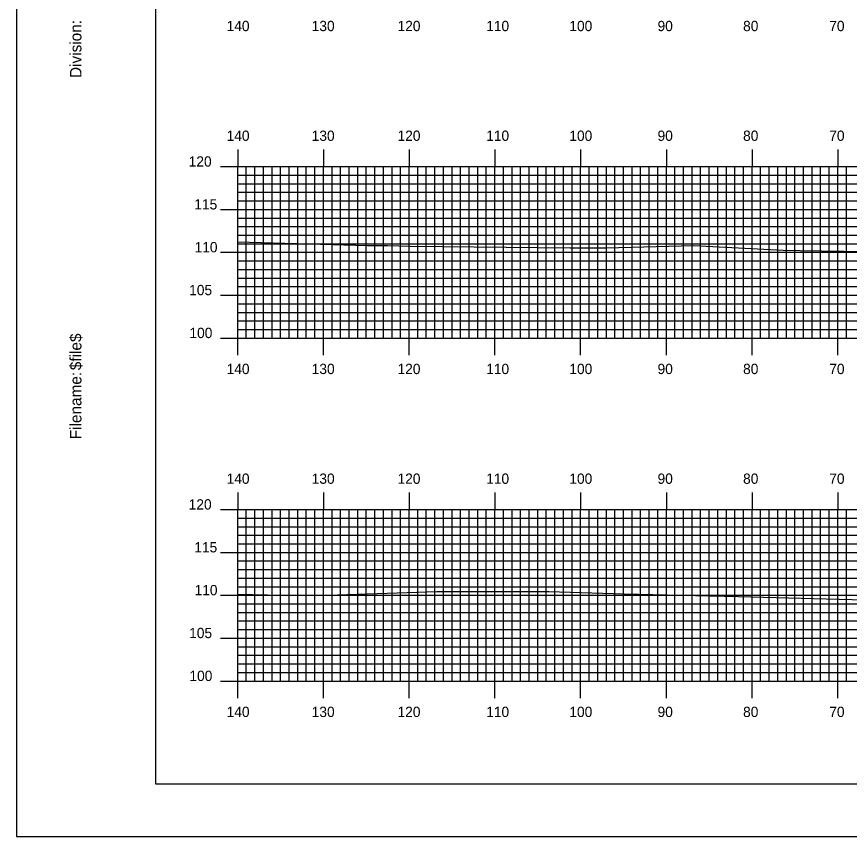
# Model space of a CAD drawing. Extents: x 1779499 to 1779842, y 442591 to 442811.
# Drawn here: x 1779499.1 to 1779596.2, y 442590.5 to 442686.2 of the extents above; entities that cross this region are included whole.
import ezdxf

# ---------------------------------------------------------------- set-up
doc = ezdxf.new("R2010")
doc.units = 0
for name, color, linetype in [('BORDER', 7, 'Continuous'), ('H_V ANNOTATION', 7, 'Continuous'), ('MAJOR', 7, 'Continuous'), ('MINOR', 7, 'Continuous'), ('PLOT BOUNDARY', 7, 'Continuous'), ('S_Roadway_Centerline', 7, 'Continuous')]:
    doc.layers.add(name, color=color, linetype=linetype)

msp = doc.modelspace()

# ---------------------------------------------------------------- linework, layer by layer
at = {"layer": 'BORDER'}
msp.add_lwpolyline([(1779515.242, 442596.665), (1779835.242, 442596.665), (1779835.242, 442806.665), (1779515.242, 442806.665)], close=True, dxfattribs=at)
at = {"layer": 'MAJOR'}
for p, q in [((1779524.842, 442670.669), (1779524.842, 442668.665)), ((1779534.842, 442670.669), (1779534.842, 442668.665)), ((1779544.842, 442670.669), (1779544.842, 442668.665)), ((1779554.842, 442670.669), (1779554.842, 442668.665)), ((1779564.842, 442670.669), (1779564.842, 442668.665)), ((1779574.842, 442670.669), (1779574.842, 442668.665)), ((1779584.842, 442670.669), (1779584.842, 442668.665)), ((1779594.842, 442670.669), (1779594.842, 442668.665)), ((1779522.838, 442668.665), (1779524.842, 442668.665)), ((1779524.842, 442668.665), (1779804.842, 442668.665)), ((1779524.842, 442648.665), (1779524.842, 442668.665)), ((1779524.842, 442648.665), (1779524.842, 442668.665)), ((1779524.842, 442668.665), (1779804.842, 442668.665)), ((1779534.842, 442648.665), (1779534.842, 442668.665)), ((1779544.842, 442648.665), (1779544.842, 442668.665)), ((1779554.842, 442648.665), (1779554.842, 442668.665)), ((1779564.842, 442648.665), (1779564.842, 442668.665)), ((1779574.842, 442648.665), (1779574.842, 442668.665)), ((1779584.842, 442648.665), (1779584.842, 442668.665)), ((1779594.842, 442648.665), (1779594.842, 442668.665)), ((1779522.838, 442663.665), (1779524.842, 442663.665)), ((1779524.842, 442663.665), (1779804.842, 442663.665)), ((1779522.838, 442658.665), (1779524.842, 442658.665)), ((1779524.842, 442658.665), (1779804.842, 442658.665)), ((1779522.838, 442653.665), (1779524.842, 442653.665)), ((1779524.842, 442653.665), (1779804.842, 442653.665)), ((1779522.838, 442648.665), (1779524.842, 442648.665)), ((1779524.842, 442648.665), (1779804.842, 442648.665)), ((1779524.842, 442648.665), (1779804.842, 442648.665)), ((1779524.842, 442646.661), (1779524.842, 442648.665)), ((1779534.842, 442646.661), (1779534.842, 442648.665)), ((1779544.842, 442646.661), (1779544.842, 442648.665)), ((1779554.842, 442646.661), (1779554.842, 442648.665)), ((1779564.842, 442646.661), (1779564.842, 442648.665)), ((1779574.842, 442646.661), (1779574.842, 442648.665)), ((1779584.842, 442646.661), (1779584.842, 442648.665)), ((1779594.842, 442646.661), (1779594.842, 442648.665)), ((1779524.842, 442630.669), (1779524.842, 442628.665)), ((1779534.842, 442630.669), (1779534.842, 442628.665)), ((1779544.842, 442630.669), (1779544.842, 442628.665)), ((1779554.842, 442630.669), (1779554.842, 442628.665)), ((1779564.842, 442630.669), (1779564.842, 442628.665)), ((1779574.842, 442630.669), (1779574.842, 442628.665)), ((1779584.842, 442630.669), (1779584.842, 442628.665)), ((1779594.842, 442630.669), (1779594.842, 442628.665)), ((1779522.838, 442628.665), (1779524.842, 442628.665)), ((1779524.842, 442628.665), (1779804.842, 442628.665)), ((1779524.842, 442608.665), (1779524.842, 442628.665)), ((1779524.842, 442608.665), (1779524.842, 442628.665)), ((1779524.842, 442628.665), (1779804.842, 442628.665)), ((1779534.842, 442608.665), (1779534.842, 442628.665)), ((1779544.842, 442608.665), (1779544.842, 442628.665)), ((1779554.842, 442608.665), (1779554.842, 442628.665)), ((1779564.842, 442608.665), (1779564.842, 442628.665)), ((1779574.842, 442608.665), (1779574.842, 442628.665)), ((1779584.842, 442608.665), (1779584.842, 442628.665)), ((1779594.842, 442608.665), (1779594.842, 442628.665)), ((1779522.838, 442623.665), (1779524.842, 442623.665)), ((1779524.842, 442623.665), (1779804.842, 442623.665)), ((1779522.838, 442618.665), (1779524.842, 442618.665)), ((1779524.842, 442618.665), (1779804.842, 442618.665)), ((1779522.838, 442613.665), (1779524.842, 442613.665)), ((1779524.842, 442613.665), (1779804.842, 442613.665)), ((1779522.838, 442608.665), (1779524.842, 442608.665)), ((1779524.842, 442608.665), (1779804.842, 442608.665)), ((1779524.842, 442608.665), (1779804.842, 442608.665)), ((1779524.842, 442606.661), (1779524.842, 442608.665)), ((1779534.842, 442606.661), (1779534.842, 442608.665)), ((1779544.842, 442606.661), (1779544.842, 442608.665)), ((1779554.842, 442606.661), (1779554.842, 442608.665)), ((1779564.842, 442606.661), (1779564.842, 442608.665)), ((1779574.842, 442606.661), (1779574.842, 442608.665)), ((1779584.842, 442606.661), (1779584.842, 442608.665)), ((1779594.842, 442606.661), (1779594.842, 442608.665))]:
    msp.add_line(p, q, dxfattribs=at)
at = {"layer": 'MINOR'}
for p, q in [((1779525.842, 442648.665), (1779525.842, 442668.665)), ((1779526.842, 442648.665), (1779526.842, 442668.665)), ((1779527.842, 442648.665), (1779527.842, 442668.665)), ((1779528.842, 442648.665), (1779528.842, 442668.665)), ((1779529.842, 442648.665), (1779529.842, 442668.665)), ((1779530.842, 442648.665), (1779530.842, 442668.665)), ((1779531.842, 442648.665), (1779531.842, 442668.665)), ((1779532.842, 442648.665), (1779532.842, 442668.665)), ((1779533.842, 442648.665), (1779533.842, 442668.665)), ((1779535.842, 442648.665), (1779535.842, 442668.665)), ((1779536.842, 442648.665), (1779536.842, 442668.665)), ((1779537.842, 442648.665), (1779537.842, 442668.665)), ((1779538.842, 442648.665), (1779538.842, 442668.665)), ((1779539.842, 442648.665), (1779539.842, 442668.665)), ((1779540.842, 442648.665), (1779540.842, 442668.665)), ((1779541.842, 442648.665), (1779541.842, 442668.665)), ((1779542.842, 442648.665), (1779542.842, 442668.665)), ((1779543.842, 442648.665), (1779543.842, 442668.665)), ((1779545.842, 442648.665), (1779545.842, 442668.665)), ((1779546.842, 442648.665), (1779546.842, 442668.665)), ((1779547.842, 442648.665), (1779547.842, 442668.665)), ((1779548.842, 442648.665), (1779548.842, 442668.665)), ((1779549.842, 442648.665), (1779549.842, 442668.665)), ((1779550.842, 442648.665), (1779550.842, 442668.665)), ((1779551.842, 442648.665), (1779551.842, 442668.665)), ((1779552.842, 442648.665), (1779552.842, 442668.665)), ((1779553.842, 442648.665), (1779553.842, 442668.665)), ((1779555.842, 442648.665), (1779555.842, 442668.665)), ((1779556.842, 442648.665), (1779556.842, 442668.665)), ((1779557.842, 442648.665), (1779557.842, 442668.665)), ((1779558.842, 442648.665), (1779558.842, 442668.665)), ((1779559.842, 442648.665), (1779559.842, 442668.665)), ((1779560.842, 442648.665), (1779560.842, 442668.665)), ((1779561.842, 442648.665), (1779561.842, 442668.665)), ((1779562.842, 442648.665), (1779562.842, 442668.665)), ((1779563.842, 442648.665), (1779563.842, 442668.665)), ((1779565.842, 442648.665), (1779565.842, 442668.665)), ((1779566.842, 442648.665), (1779566.842, 442668.665)), ((1779567.842, 442648.665), (1779567.842, 442668.665)), ((1779568.842, 442648.665), (1779568.842, 442668.665)), ((1779569.842, 442648.665), (1779569.842, 442668.665)), ((1779570.842, 442648.665), (1779570.842, 442668.665)), ((1779571.842, 442648.665), (1779571.842, 442668.665)), ((1779572.842, 442648.665), (1779572.842, 442668.665)), ((1779573.842, 442648.665), (1779573.842, 442668.665)), ((1779575.842, 442648.665), (1779575.842, 442668.665)), ((1779576.842, 442648.665), (1779576.842, 442668.665)), ((1779577.842, 442648.665), (1779577.842, 442668.665)), ((1779578.842, 442648.665), (1779578.842, 442668.665)), ((1779579.842, 442648.665), (1779579.842, 442668.665)), ((1779580.842, 442648.665), (1779580.842, 442668.665)), ((1779581.842, 442648.665), (1779581.842, 442668.665)), ((1779582.842, 442648.665), (1779582.842, 442668.665)), ((1779583.842, 442648.665), (1779583.842, 442668.665)), ((1779585.842, 442648.665), (1779585.842, 442668.665)), ((1779586.842, 442648.665), (1779586.842, 442668.665)), ((1779587.842, 442648.665), (1779587.842, 442668.665)), ((1779588.842, 442648.665), (1779588.842, 442668.665)), ((1779589.842, 442648.665), (1779589.842, 442668.665)), ((1779590.842, 442648.665), (1779590.842, 442668.665)), ((1779591.842, 442648.665), (1779591.842, 442668.665)), ((1779592.842, 442648.665), (1779592.842, 442668.665)), ((1779593.842, 442648.665), (1779593.842, 442668.665)), ((1779595.842, 442648.665), (1779595.842, 442668.665)), ((1779524.842, 442667.665), (1779804.842, 442667.665)), ((1779524.842, 442667.665), (1779526.846, 442667.665)), ((1779524.842, 442666.665), (1779804.842, 442666.665)), ((1779524.842, 442666.665), (1779526.846, 442666.665)), ((1779524.842, 442665.665), (1779804.842, 442665.665)), ((1779524.842, 442665.665), (1779526.846, 442665.665)), ((1779524.842, 442664.665), (1779804.842, 442664.665)), ((1779524.842, 442664.665), (1779526.846, 442664.665)), ((1779524.842, 442662.665), (1779804.842, 442662.665)), ((1779524.842, 442662.665), (1779526.846, 442662.665)), ((1779524.842, 442661.665), (1779804.842, 442661.665)), ((1779524.842, 442661.665), (1779526.846, 442661.665)), ((1779524.842, 442660.665), (1779804.842, 442660.665)), ((1779524.842, 442660.665), (1779526.846, 442660.665)), ((1779524.842, 442659.665), (1779804.842, 442659.665)), ((1779524.842, 442659.665), (1779526.846, 442659.665)), ((1779524.842, 442657.665), (1779804.842, 442657.665)), ((1779524.842, 442657.665), (1779526.846, 442657.665)), ((1779524.842, 442656.665), (1779804.842, 442656.665)), ((1779524.842, 442656.665), (1779526.846, 442656.665)), ((1779524.842, 442655.665), (1779804.842, 442655.665)), ((1779524.842, 442655.665), (1779526.846, 442655.665)), ((1779524.842, 442654.665), (1779804.842, 442654.665)), ((1779524.842, 442654.665), (1779526.846, 442654.665)), ((1779524.842, 442652.665), (1779804.842, 442652.665)), ((1779524.842, 442652.665), (1779526.846, 442652.665)), ((1779524.842, 442651.665), (1779804.842, 442651.665)), ((1779524.842, 442651.665), (1779526.846, 442651.665)), ((1779524.842, 442650.665), (1779804.842, 442650.665)), ((1779524.842, 442650.665), (1779526.846, 442650.665)), ((1779524.842, 442649.665), (1779804.842, 442649.665)), ((1779524.842, 442649.665), (1779526.846, 442649.665)), ((1779525.842, 442608.665), (1779525.842, 442628.665)), ((1779526.842, 442608.665), (1779526.842, 442628.665)), ((1779527.842, 442608.665), (1779527.842, 442628.665)), ((1779528.842, 442608.665), (1779528.842, 442628.665)), ((1779529.842, 442608.665), (1779529.842, 442628.665)), ((1779530.842, 442608.665), (1779530.842, 442628.665)), ((1779531.842, 442608.665), (1779531.842, 442628.665)), ((1779532.842, 442608.665), (1779532.842, 442628.665)), ((1779533.842, 442608.665), (1779533.842, 442628.665)), ((1779535.842, 442608.665), (1779535.842, 442628.665)), ((1779536.842, 442608.665), (1779536.842, 442628.665)), ((1779537.842, 442608.665), (1779537.842, 442628.665)), ((1779538.842, 442608.665), (1779538.842, 442628.665)), ((1779539.842, 442608.665), (1779539.842, 442628.665)), ((1779540.842, 442608.665), (1779540.842, 442628.665)), ((1779541.842, 442608.665), (1779541.842, 442628.665)), ((1779542.842, 442608.665), (1779542.842, 442628.665)), ((1779543.842, 442608.665), (1779543.842, 442628.665)), ((1779545.842, 442608.665), (1779545.842, 442628.665)), ((1779546.842, 442608.665), (1779546.842, 442628.665)), ((1779547.842, 442608.665), (1779547.842, 442628.665)), ((1779548.842, 442608.665), (1779548.842, 442628.665)), ((1779549.842, 442608.665), (1779549.842, 442628.665)), ((1779550.842, 442608.665), (1779550.842, 442628.665)), ((1779551.842, 442608.665), (1779551.842, 442628.665)), ((1779552.842, 442608.665), (1779552.842, 442628.665)), ((1779553.842, 442608.665), (1779553.842, 442628.665)), ((1779555.842, 442608.665), (1779555.842, 442628.665)), ((1779556.842, 442608.665), (1779556.842, 442628.665)), ((1779557.842, 442608.665), (1779557.842, 442628.665)), ((1779558.842, 442608.665), (1779558.842, 442628.665)), ((1779559.842, 442608.665), (1779559.842, 442628.665)), ((1779560.842, 442608.665), (1779560.842, 442628.665)), ((1779561.842, 442608.665), (1779561.842, 442628.665)), ((1779562.842, 442608.665), (1779562.842, 442628.665)), ((1779563.842, 442608.665), (1779563.842, 442628.665)), ((1779565.842, 442608.665), (1779565.842, 442628.665)), ((1779566.842, 442608.665), (1779566.842, 442628.665)), ((1779567.842, 442608.665), (1779567.842, 442628.665)), ((1779568.842, 442608.665), (1779568.842, 442628.665)), ((1779569.842, 442608.665), (1779569.842, 442628.665)), ((1779570.842, 442608.665), (1779570.842, 442628.665)), ((1779571.842, 442608.665), (1779571.842, 442628.665)), ((1779572.842, 442608.665), (1779572.842, 442628.665)), ((1779573.842, 442608.665), (1779573.842, 442628.665)), ((1779575.842, 442608.665), (1779575.842, 442628.665)), ((1779576.842, 442608.665), (1779576.842, 442628.665)), ((1779577.842, 442608.665), (1779577.842, 442628.665)), ((1779578.842, 442608.665), (1779578.842, 442628.665)), ((1779579.842, 442608.665), (1779579.842, 442628.665)), ((1779580.842, 442608.665), (1779580.842, 442628.665)), ((1779581.842, 442608.665), (1779581.842, 442628.665)), ((1779582.842, 442608.665), (1779582.842, 442628.665)), ((1779583.842, 442608.665), (1779583.842, 442628.665)), ((1779585.842, 442608.665), (1779585.842, 442628.665)), ((1779586.842, 442608.665), (1779586.842, 442628.665)), ((1779587.842, 442608.665), (1779587.842, 442628.665)), ((1779588.842, 442608.665), (1779588.842, 442628.665)), ((1779589.842, 442608.665), (1779589.842, 442628.665)), ((1779590.842, 442608.665), (1779590.842, 442628.665)), ((1779591.842, 442608.665), (1779591.842, 442628.665)), ((1779592.842, 442608.665), (1779592.842, 442628.665)), ((1779593.842, 442608.665), (1779593.842, 442628.665)), ((1779595.842, 442608.665), (1779595.842, 442628.665)), ((1779524.842, 442627.665), (1779804.842, 442627.665)), ((1779524.842, 442627.665), (1779526.846, 442627.665)), ((1779524.842, 442626.665), (1779804.842, 442626.665)), ((1779524.842, 442626.665), (1779526.846, 442626.665)), ((1779524.842, 442625.665), (1779804.842, 442625.665)), ((1779524.842, 442625.665), (1779526.846, 442625.665)), ((1779524.842, 442624.665), (1779804.842, 442624.665)), ((1779524.842, 442624.665), (1779526.846, 442624.665)), ((1779524.842, 442622.665), (1779804.842, 442622.665)), ((1779524.842, 442622.665), (1779526.846, 442622.665)), ((1779524.842, 442621.665), (1779804.842, 442621.665)), ((1779524.842, 442621.665), (1779526.846, 442621.665)), ((1779524.842, 442620.665), (1779804.842, 442620.665)), ((1779524.842, 442620.665), (1779526.846, 442620.665)), ((1779524.842, 442619.665), (1779804.842, 442619.665)), ((1779524.842, 442619.665), (1779526.846, 442619.665)), ((1779524.842, 442617.665), (1779804.842, 442617.665)), ((1779524.842, 442617.665), (1779526.846, 442617.665)), ((1779524.842, 442616.665), (1779804.842, 442616.665)), ((1779524.842, 442616.665), (1779526.846, 442616.665)), ((1779524.842, 442615.665), (1779804.842, 442615.665)), ((1779524.842, 442615.665), (1779526.846, 442615.665)), ((1779524.842, 442614.665), (1779804.842, 442614.665)), ((1779524.842, 442614.665), (1779526.846, 442614.665)), ((1779524.842, 442612.665), (1779804.842, 442612.665)), ((1779524.842, 442612.665), (1779526.846, 442612.665)), ((1779524.842, 442611.665), (1779804.842, 442611.665)), ((1779524.842, 442611.665), (1779526.846, 442611.665)), ((1779524.842, 442610.665), (1779804.842, 442610.665)), ((1779524.842, 442610.665), (1779526.846, 442610.665)), ((1779524.842, 442609.665), (1779804.842, 442609.665)), ((1779524.842, 442609.665), (1779526.846, 442609.665))]:
    msp.add_line(p, q, dxfattribs=at)
at = {"layer": 'PLOT BOUNDARY'}
msp.add_lwpolyline([(1779499.056, 442590.547), (1779839.056, 442590.547), (1779839.056, 442810.547), (1779499.056, 442810.547)], close=True, dxfattribs=at)
at = {"layer": 'S_Roadway_Centerline'}
for points in [[(1779524.842, 442659.876), (1779539.981, 442659.456), (1779542.332, 442659.471), (1779544.971, 442659.371), (1779563.612, 442659.176), (1779567.847, 442659.178), (1779578.002, 442659.476), (1779588.471, 442658.908), (1779590.47, 442658.874), (1779613.363, 442658.531), (1779613.974, 442658.519), (1779633.708, 442658.202), (1779633.943, 442658.196), (1779634.255, 442658.208), (1779647.624, 442658.69), (1779656.692, 442658.51), (1779657.627, 442658.513), (1779669.743, 442658.695), (1779679.849, 442658.136), (1779684.372, 442658.083), (1779694.365, 442658.528), (1779704.273, 442658.023), (1779707.725, 442657.909), (1779724.688, 442657.781)], [(1779524.842, 442618.787), (1779530.014, 442618.672), (1779535.321, 442618.687), (1779548.073, 442619.115), (1779561.142, 442619.114), (1779569.915, 442618.82), (1779583.271, 442618.54), (1779593.483, 442618.248), (1779607.158, 442617.888), (1779610.65, 442617.932), (1779614.506, 442617.842), (1779630.747, 442617.757), (1779637.646, 442617.813), (1779653.858, 442617.87), (1779661.057, 442617.687), (1779672.256, 442617.348), (1779677.716, 442617.301), (1779692.079, 442617.401), (1779701.614, 442617.01), (1779706.692, 442616.876), (1779709.872, 442617.024), (1779717.478, 442617.159), (1779727.575, 442616.982)]]:
    msp.add_lwpolyline(points, dxfattribs=at)

# ---------------------------------------------------------------- texts
at = {"layer": 'BORDER'}
for s, p in [('Division:', (1779506.612, 442678.997)), ('$file$', (1779506.612, 442644.916)), ('Filename:', (1779506.612, 442636.862))]:
    msp.add_text(s, height=1.3392, rotation=90, dxfattribs=at).set_placement(p)
at = {"layer": 'H_V ANNOTATION'}
for s, p in [('140', (1779523.547, 442684.465)), ('130', (1779533.472, 442684.465)), ('120', (1779543.483, 442684.465)), ('110', (1779553.826, 442684.465)), ('100', (1779563.526, 442684.465)), ('90', (1779573.815, 442684.465)), ('80', (1779583.793, 442684.465)), ('70', (1779593.846, 442684.465)), ('140', (1779523.547, 442671.665)), ('130', (1779533.472, 442671.665)), ('120', (1779543.483, 442671.665)), ('110', (1779553.826, 442671.665)), ('100', (1779563.526, 442671.665)), ('90', (1779573.815, 442671.665)), ('80', (1779583.793, 442671.665)), ('70', (1779593.846, 442671.665)), ('120', (1779519.123, 442668.665)), ('115', (1779519.777, 442663.665)), ('110', (1779519.809, 442658.665)), ('105', (1779519.177, 442653.665)), ('100', (1779519.209, 442648.665)), ('140', (1779523.547, 442644.465)), ('130', (1779533.472, 442644.465)), ('120', (1779543.483, 442644.465)), ('110', (1779553.826, 442644.465)), ('100', (1779563.526, 442644.465)), ('90', (1779573.815, 442644.465)), ('80', (1779583.793, 442644.465)), ('70', (1779593.846, 442644.465)), ('140', (1779523.547, 442631.665)), ('130', (1779533.472, 442631.665)), ('120', (1779543.483, 442631.665)), ('110', (1779553.826, 442631.665)), ('100', (1779563.526, 442631.665)), ('90', (1779573.815, 442631.665)), ('80', (1779583.793, 442631.665)), ('70', (1779593.846, 442631.665)), ('120', (1779519.123, 442628.665)), ('115', (1779519.777, 442623.665)), ('110', (1779519.809, 442618.665)), ('105', (1779519.177, 442613.665)), ('100', (1779519.209, 442608.665)), ('140', (1779523.547, 442604.465)), ('130', (1779533.472, 442604.465)), ('120', (1779543.483, 442604.465)), ('110', (1779553.826, 442604.465)), ('100', (1779563.526, 442604.465)), ('90', (1779573.815, 442604.465)), ('80', (1779583.793, 442604.465)), ('70', (1779593.846, 442604.465))]:
    msp.add_text(s, height=1.2, dxfattribs=at).set_placement(p)
at = {"layer": 'MAJOR'}
for p in [(1779524.833, 442648.665), (1779524.833, 442608.665)]:
    msp.add_text('-', height=0.012, dxfattribs=at).set_placement(p)

doc.saveas('drawing.dxf')
